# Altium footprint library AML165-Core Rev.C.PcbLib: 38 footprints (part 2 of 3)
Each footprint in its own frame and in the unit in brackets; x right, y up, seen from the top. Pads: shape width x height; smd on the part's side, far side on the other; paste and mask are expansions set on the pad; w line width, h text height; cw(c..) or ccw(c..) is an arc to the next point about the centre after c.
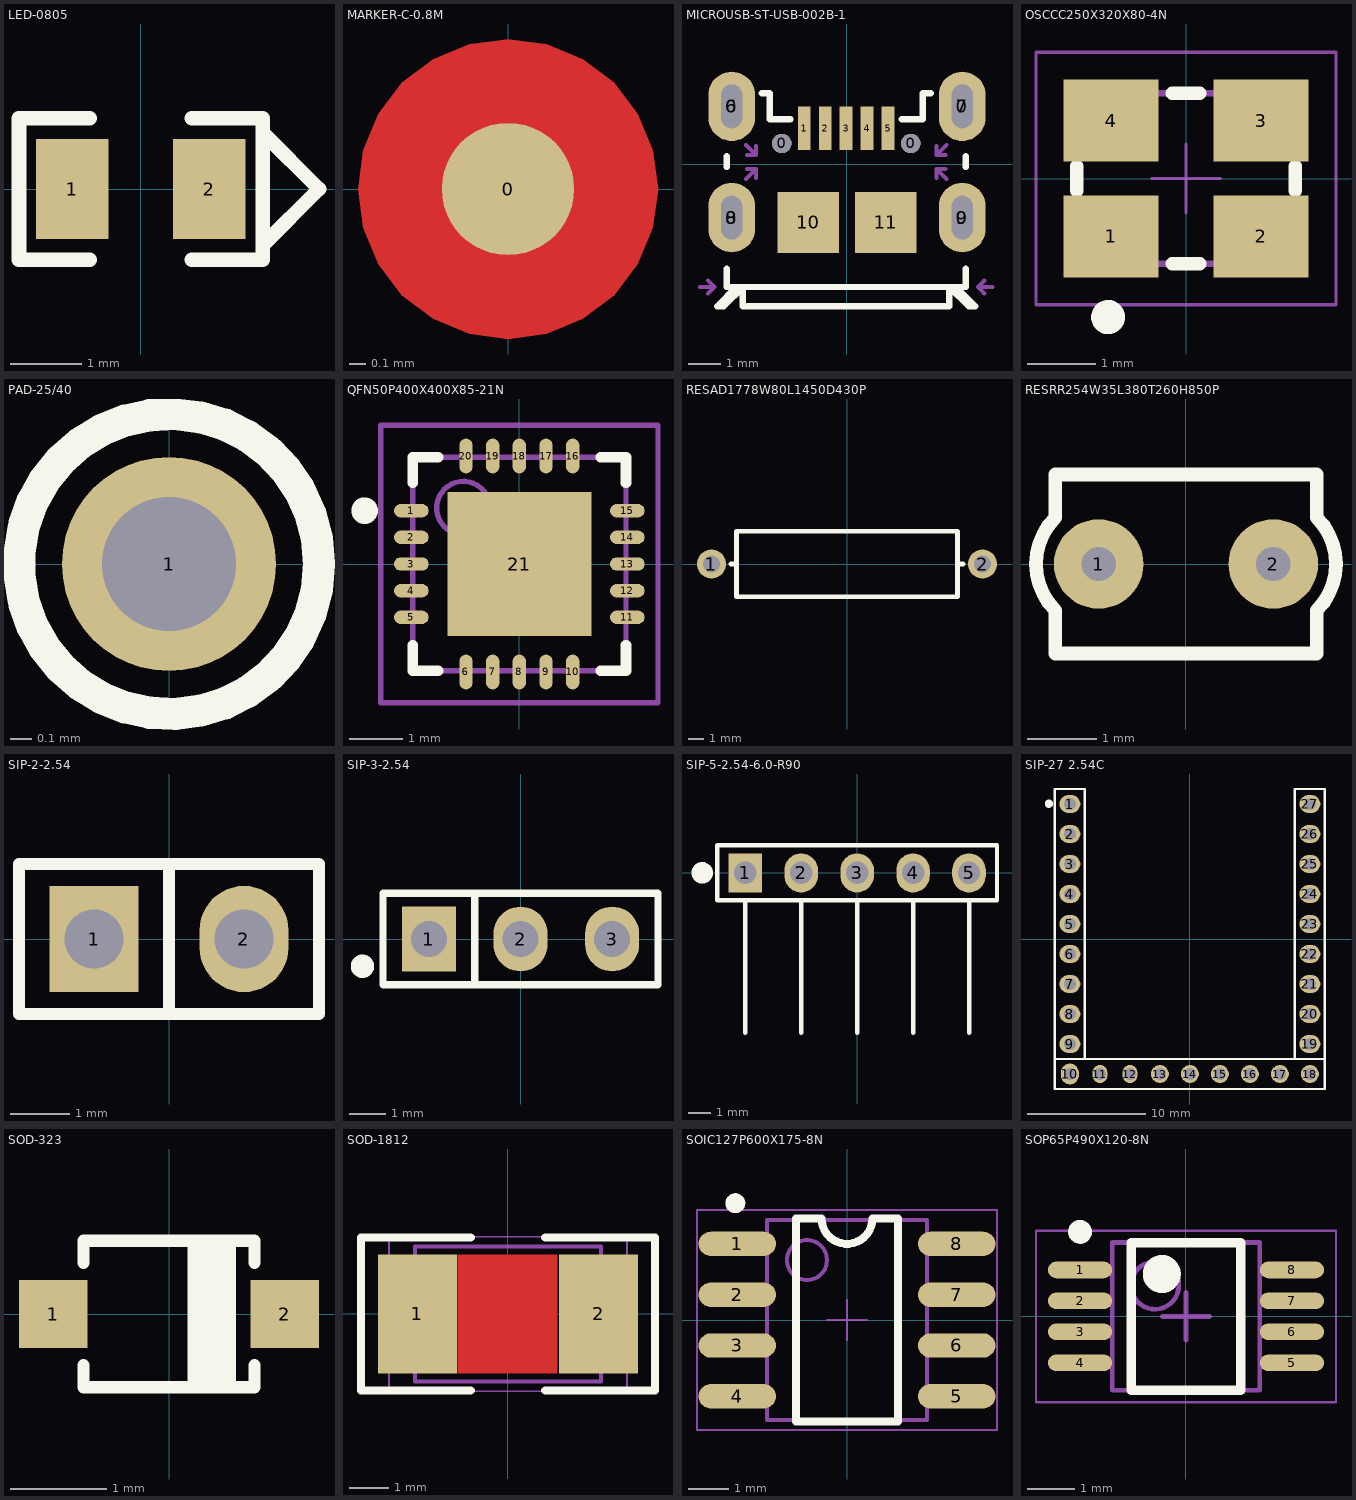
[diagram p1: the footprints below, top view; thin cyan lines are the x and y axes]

## LED-0805 [mm] "170907内距改0.9mm"
pads (2):
  rect 1.014x1.4 smd: 1(-0.957,0) 2(0.957,0)
Top Overlay:
  lines w0.203: -0.711,-0.991 -1.702,-0.991 -1.702,0.991 -0.711,0.991 ; 0.711,-0.991 1.702,-0.991 1.702,0.991 0.711,0.991 ; 1.702,-0.787 2.489,0 1.702,0.787
3D body: height 0.64, standoff 0, extent -1,-0.635 1,0.635
3D body: height 1.1, standoff 0, extent -0.508,-0.508 0.508,0.508

## MARKER-C-0.8M [mm]
pads (1):
  round 0.8 smd paste-1.016 mask+0.4: 0(0,0)
Top Layer:
  pour cut-out: -0.908,0 -0.877,-0.235 -0.786,-0.454 -0.642,-0.642 -0.454,-0.786 -0.235,-0.877 0,-0.908 0.235,-0.877 0.454,-0.786 0.642,-0.642 0.786,-0.454 0.877,-0.235 0.908,0 0.877,0.235 0.786,0.454 0.642,0.642 0.454,0.786 0.235,0.877 0,0.908 -0.235,0.877 -0.454,0.786 -0.642,0.642 -0.786,0.454 -0.877,0.235

## MICROUSB-ST-USB-002B-1 [mm]
height 3
pads (17):
  oval 1.45x2.15 on Top Paste: 0(-3.575,-1.65) 0(-3.575,1.8) 0(3.575,-1.65) 0(3.575,1.8)
  round 0.6 hole 0.6 unplated: 0(-2.025,0.65) 0(1.975,0.65)
  rect 0.4x1.35 smd: 1(-1.325,1.115) 2(-0.675,1.115) 3(-0.025,1.115) 4(0.625,1.115) 5(1.275,1.115)
  oval 1.45x2.15 hole 0.65 slot 1.35 at 90 deg: 6(-3.575,1.8) 7(3.575,1.8) 8(-3.575,-1.65) 9(3.575,-1.65)
  rect 1.9x1.9 smd: 10(-1.2,-1.8) 11(1.2,-1.8)
Top Overlay:
  lines w0.2: -3.725,-3.234 -3.725,-3.8 3.675,-3.8 3.675,-3.234 ; -3.725,-0.081 -3.725,0.246 ; -3.425,-3.8 -4.025,-4.4 -3.825,-4.4 -3.225,-3.8 -3.225,-4.4 3.175,-4.4 3.175,-3.8 3.775,-4.4 3.975,-4.4 3.375,-3.8 ; -2.641,2.2 -2.4,2.2 -2.4,1.4 -1.752,1.4 ; 1.702,1.4 2.35,1.4 2.35,2.2 2.591,2.2 ; 3.675,-0.081 3.675,0.246
Mechanical 15:
  lines w0.127: -4.556,-3.8 -4.106,-3.8 ; -4.306,-4 -4.106,-3.8 ; -4.306,-3.6 -4.106,-3.8 ; -3.137,-0.455 -2.819,-0.137 ; -3.137,0.605 -2.819,0.287 ; -3.102,-0.137 -2.819,-0.137 ; -3.102,0.287 -2.819,0.287 ; -2.819,-0.42 -2.819,-0.137 ; -2.819,0.57 -2.819,0.287 ; 2.769,-0.42 2.769,-0.137 ; 2.769,0.57 2.769,0.287 ; 3.052,-0.137 2.769,-0.137 ; 3.052,0.287 2.769,0.287 ; 3.087,-0.455 2.769,-0.137 ; 3.087,0.605 2.769,0.287 ; 4.256,-4 4.056,-3.8 ; 4.256,-3.6 4.056,-3.8 ; 4.506,-3.8 4.056,-3.8
  text "PCB EDGE" at -1.905,-4.064 h0.51
  text "TopPaste" at -1.499,-0.412 h0.51

## OSCCC250X320X80-4N [mm]
height 0.8
pads (4):
  rect 1.4x1.2 smd: 1(-1.1,-0.85) 2(1.1,-0.85) 3(1.1,0.85) 4(-1.1,0.85)
Top Overlay:
  circle w0.25: c-1.143,-2.032 r0.125
  lines w0.2: -1.6,-0.178 -1.6,0.178 ; -0.203,-1.25 0.203,-1.25 ; -0.203,1.25 0.203,1.25 ; 1.6,-0.178 1.6,0.178
Mechanical 13:
  lines w0.1: -1.6,-1.15 -1.5,-1.25 ; -1.6,-1.05 -1.4,-1.25 ; -1.6,-0.95 -1.3,-1.25 ; -1.6,-0.85 -1.2,-1.25 ; -1.6,-0.75 -1.1,-1.25 ; -1.6,-0.65 -1,-1.25 ; -1.6,-0.55 -0.9,-1.25 ; -1.6,-0.45 -0.8,-1.25 ; -1.6,-0.35 -0.7,-1.25 ; -1.6,-0.25 -0.6,-1.25 ; -1.6,-1.25 -1.6,1.25 1.6,1.25 1.6,-1.25 -1.6,-1.25
Mechanical 15:
  lines w0.05: -0.5,0 0.5,0 ; 0,-0.5 0,0.5 ; -2.2,-1.85 -2.2,1.85 2.2,1.85 2.2,-1.85 -2.2,-1.85

## PAD-25/40 [mil]
height 5
pads (1):
  round 40 hole 25: 1(0,0)
Top Overlay:
  circle w6: c0,0 r28

## QFN50P400X400X85-21N [mm] "QFN, 20-Leads, Body 4.0x4.0mm (max), Pitch 0.50mm, IPC Medium Density"
height 0.85
pads (21):
  oval 0.65x0.25 smd: 1(-2.025,1) 2(-2.025,0.5) 3(-2.025,0) 4(-2.025,-0.5) 5(-2.025,-1) 11(2.025,-1) 12(2.025,-0.5) 13(2.025,0) 14(2.025,0.5) 15(2.025,1)
  oval 0.25x0.65 smd: 6(-1,-2.025) 7(-0.5,-2.025) 8(0,-2.025) 9(0.5,-2.025) 10(1,-2.025) 16(1,2.025) 17(0.5,2.025) 18(0,2.025) 19(-0.5,2.025) 20(-1,2.025)
  rect 2.7x2.7 smd: 21(0,0)
Top Overlay:
  circle w0.25: c-2.9,1 r0.125
  lines w0.2: -2,-1.525 -2,-2 -1.525,-2 ; -2,1.525 -2,2 -1.525,2 ; 1.525,-2 2,-2 2,-1.525 ; 1.525,2 2,2 2,1.525
Mechanical 13:
  circle w0.1: c-1.05,1.05 r0.5
  lines w0.1: -2,-2 -2,2 2,2 2,-2 -2,-2
Mechanical 15:
  lines w0.1: -0.5,0 0.5,0 ; 0,-0.5 0,0.5 ; -2.6,-2.6 -2.6,2.6 2.6,2.6 2.6,-2.6 -2.6,-2.6
3D body: height 0.85, standoff 0.02, extent -2,-2 2,2

## RESAD1778W80L1450D430P [mm]
height 1.905
pads (2):
  round 1.9 hole 1.1: 1(-8.89,0) 2(8.89,0)
Top Overlay:
  lines w0.305: -7.62,0 -7.239,0 ; 7.239,0 7.62,0 ; -7.25,-2.15 7.25,-2.15 7.25,2.15 -7.25,2.15 -7.25,-2.15

## RESRR254W35L380T260H850P [mm]
height 8.5
pads (2):
  round 1.3 hole 0.5: 1(-1.27,0) 2(1.27,0)
Top Overlay:
  lines w0.2: -1.9,-1.3 -1.9,-0.675 cw(c-1.225,0) -1.9,0.675 -1.9,1.3 1.9,1.3 1.9,0.675 cw(c1.225,0) 1.9,-0.675 1.9,-1.3 -1.9,-1.3

## SIP-2-2.54 [mm]
pads (2):
  rect 1.5x1.8 hole 1: 1(-1.27,0)
  oval 1.5x1.8 hole 1: 2(1.27,0)
Top Overlay:
  lines w0.2: 0,-1.27 0,1.27 ; -2.54,-1.27 -2.54,1.27 2.54,1.27 2.54,-1.27 -2.54,-1.27
3D body: height 7.58, standoff -2.94, extent -2.54,-1.27 0,1.27
3D body: height 7.58, standoff -2.94, extent 0,-1.27 2.54,1.27

## SIP-3-2.54 [mm]
pads (3):
  rect 1.5x1.8 hole 1: 1(-2.54,0)
  oval 1.5x1.8 hole 1: 2(0,0) 3(2.54,0)
Top Overlay:
  circle w0.4: c-4.381,-0.756 r0.125
  lines w0.2: -1.27,-1.27 -1.27,1.27 ; -3.81,-1.27 3.81,-1.27 3.81,1.27 -3.81,1.27 -3.81,-1.27
3D body: height 7.58, standoff -2.94, extent 1.27,-1.27 3.81,1.27
3D body: height 7.58, standoff -2.94, extent -1.27,-1.27 1.27,1.27
3D body: height 7.58, standoff -2.94, extent -3.81,-1.27 -1.27,1.27

## SIP-5-2.54-6.0-R90 [mil] "引脚伸出部分为6.0mm"
pads (5):
  rect 60x70 hole 40: 1(-200,0)
  oval 60x70 hole 40: 2(-100,0) 3(0,0) 4(100,0) 5(200,0)
Top Overlay:
  circle w20: c-277,0.22 r9.22
  lines w8: -200,-285.43 -200,-49.21 ; -100,-285.43 -100,-49.21 ; 0,-285.43 0,-49.21 ; 100,-285.43 100,-49.21 ; 200,-285.43 200,-49.21 ; -250,-49.21 -250,49.21 250,49.21 250,-49.21 -250,-49.21

## SIP-27 2.54C [mil]
pads (27):
  oval 70x60 hole 40: 1(-400,450) 2(-400,350) 3(-400,250) 4(-400,150) 5(-400,50) 6(-400,-50) 7(-400,-150) 8(-400,-250) 9(-400,-350) 19(400,-350) 20(400,-250) 21(400,-150) 22(400,-50) 23(400,50) 24(400,150) 25(400,250) 26(400,350) 27(400,450)
  oval 60x70 hole 40: 10(-400,-450)
  oval 50x60 / inner oval 60x70 / far side oval 60x70 hole 40: 11(-300,-450) 12(-200,-450)
  round 60 / inner oval 60x70 / far side oval 60x70 hole 40: 13(-100,-450) 14(0,-450) 15(100,-450) 16(200,-450) 17(300,-450) 18(400,-450)
Top Overlay:
  circle w15.75: c-469.94,450.98 r5.91
  lines w8: 445,-400 -450,-400 ; 448.82,-500 -450,-500 -450,-400 ; 450,-500 450,-400 ; -450,-400 -350,-400 -350,500 -450,500 -450,-400 ; 450,-400 450,500 350,500 350,-400 450,-400

## SOD-323 [mil]
height 38
pads (2):
  rect 28x28 smd: 1(-47.5,0) 2(47.5,0)
Top Overlay:
  lines w5: -35,-21 -35,-30 35,-30 35,-21 ; -35,21 -35,30 35,30 35,21 ; 10,-30 10,30 ; 15,-30 15,30 ; 20,-30 20,30 ; 25,-30 25,30
3D body: height 39.37, standoff 0, extent -51,-26 51.36,25.18

## SOD-1812 [mm]
height 2.032
pads (2):
  rect 2x3 smd: 1(-2.286,0) 2(2.286,0)
Top Layer:
  pour cut-out: -1.27,1.499 -1.27,-1.499 1.245,-1.499 1.245,1.499
Top Overlay:
  lines w0.203: -3.2,1.93 -0.94,1.93 -3.708,1.93 -3.708,-1.93 -0.94,-1.93 ; 0.94,-1.93 3.708,-1.93 3.708,1.93 0.94,1.93
Mechanical 15:
  lines w0.1: -2.35,-1.7 2.35,-1.7 2.35,1.7 -2.35,1.7 -2.35,-1.7
  text "1" at -0.178,-0.356 h0.75
Mechanical 16:
  lines w0.001: -2.35,-1.7 2.35,-1.7 2.35,1.7 -2.35,1.7 -2.35,-1.7
  lines w0.05: -0.5,0 0.5,0 ; 0,-0.5 0,0.5 ; -3,-1.95 3,-1.95 3,1.95 -3,1.95 -3,-1.95

## SOIC127P600X175-8N [mil]
height 68.9
pads (8):
  oval 76.06x24 smd: 1(-108.03,75) 2(-108.03,25) 3(-108.03,-25) 4(-108.03,-75) 5(108.03,-75) 6(108.03,-25) 7(108.03,25) 8(108.03,75)
Top Overlay:
  circle w9.84: c-109.92,115 r4.92
  lines w7.87: -50,-100 -50,100 -25,100 ccw(c0,100) 25,100 50,100 50,-100 -50,-100
Mechanical 15:
  circle w3.94: c-39.37,59.06 r19.68
  lines w3.94: -78.74,-98.43 78.74,-98.43 78.74,98.43 -78.74,98.43 -78.74,-98.43
  text "1" at 17.71,-6.47 h29.53
Mechanical 16:
  lines w0.04: -78.74,-98.43 78.74,-98.43 78.74,98.43 -78.74,98.43 -78.74,-98.43
  lines w1.97: -19.68,0 19.68,0 ; 0,-19.68 0,19.68 ; -147.64,-108.27 147.64,-108.27 147.64,108.27 -147.64,108.27 -147.64,-108.27
3D body: height 61.02, standoff -1.97, extent -117.91,-96 117.91,96.91

## SOP65P490X120-8N [mm] "TSOP, 8-Leads, Body 3.00x3.00mm, Pitch 0.65mm, IPC Medium Density"
height 1.2
pads (8):
  oval 1.35x0.35 smd: 1(-2.225,0.975) 2(-2.225,0.325) 3(-2.225,-0.325) 4(-2.225,-0.975) 5(2.225,-0.975) 6(2.225,-0.325) 7(2.225,0.325) 8(2.225,0.975)
Top Overlay:
  circle w0.4: c-0.508,0.889 r0.2
  circle w0.25: c-2.225,1.775 r0.125
  lines w0.2: -1.15,-1.55 1.15,-1.55 1.15,1.55 -1.15,1.55 -1.15,-1.55
Mechanical 13:
  circle w0.1: c-0.65,0.65 r0.5
  lines w0.1: -1.55,-1.55 1.55,-1.55 1.55,1.55 -1.55,1.55 -1.55,-1.55
Mechanical 15:
  lines w0.05: -3.15,-1.8 3.15,-1.8 3.15,1.8 -3.15,1.8 -3.15,-1.8
  lines w0.1: -0.5,0 0.5,0 ; 0,-0.5 0,0.5
3D body: height 1.2, standoff 0, extent -1.55,-1.55 1.55,1.55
